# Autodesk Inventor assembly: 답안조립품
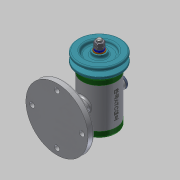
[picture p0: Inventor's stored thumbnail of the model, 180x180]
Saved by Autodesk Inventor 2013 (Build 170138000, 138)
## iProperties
Created: 2018-12
Part Number: 답안조립품
Document SubType Name: Assembly
Designer: Gpr
Author: Gpr
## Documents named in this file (15)
- C:\Users\Administrator\Desktop\481207V1071\답안조립품.iam
- C:\Users\Administrator\Desktop\481207V1071\본체.ipt
- C:\Users\Administrator\Desktop\481207V1071\V벨트풀리.ipt
- C:\Users\Administrator\Desktop\481207V1071\고무캡.ipt
- C:\Users\Administrator\Desktop\481207V1071\너트 M8.ipt
- 너트 M8.ipt
- C:\Users\Administrator\Desktop\481207V1071\뒤커버.ipt
- C:\Users\Administrator\Desktop\481207V1071\베어링 15 x 32 x 9.ipt
- C:\Users\Administrator\Desktop\481207V1071\볼트 M4 x 12.ipt
- C:\Users\Administrator\Desktop\481207V1071\스프링와셔 8.ipt
- C:\Users\Administrator\Desktop\481207V1071\앞커버.ipt
- C:\Users\Administrator\Desktop\481207V1071\오일 실 15 25 7.ipt
- C:\Users\Administrator\Desktop\481207V1071\와셔 8x17.ipt
- C:\Users\Administrator\Desktop\481207V1071\축.ipt
- C:\Users\Administrator\Desktop\481207V1071\키 3 x 3 x 12.ipt
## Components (2 placed, 2 different names)
1. V벨트풀리:1
2. 고무캡:1 — 각도:1
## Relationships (1: Angle 1)
- 각도:1 [Angle]: 고무캡:1
